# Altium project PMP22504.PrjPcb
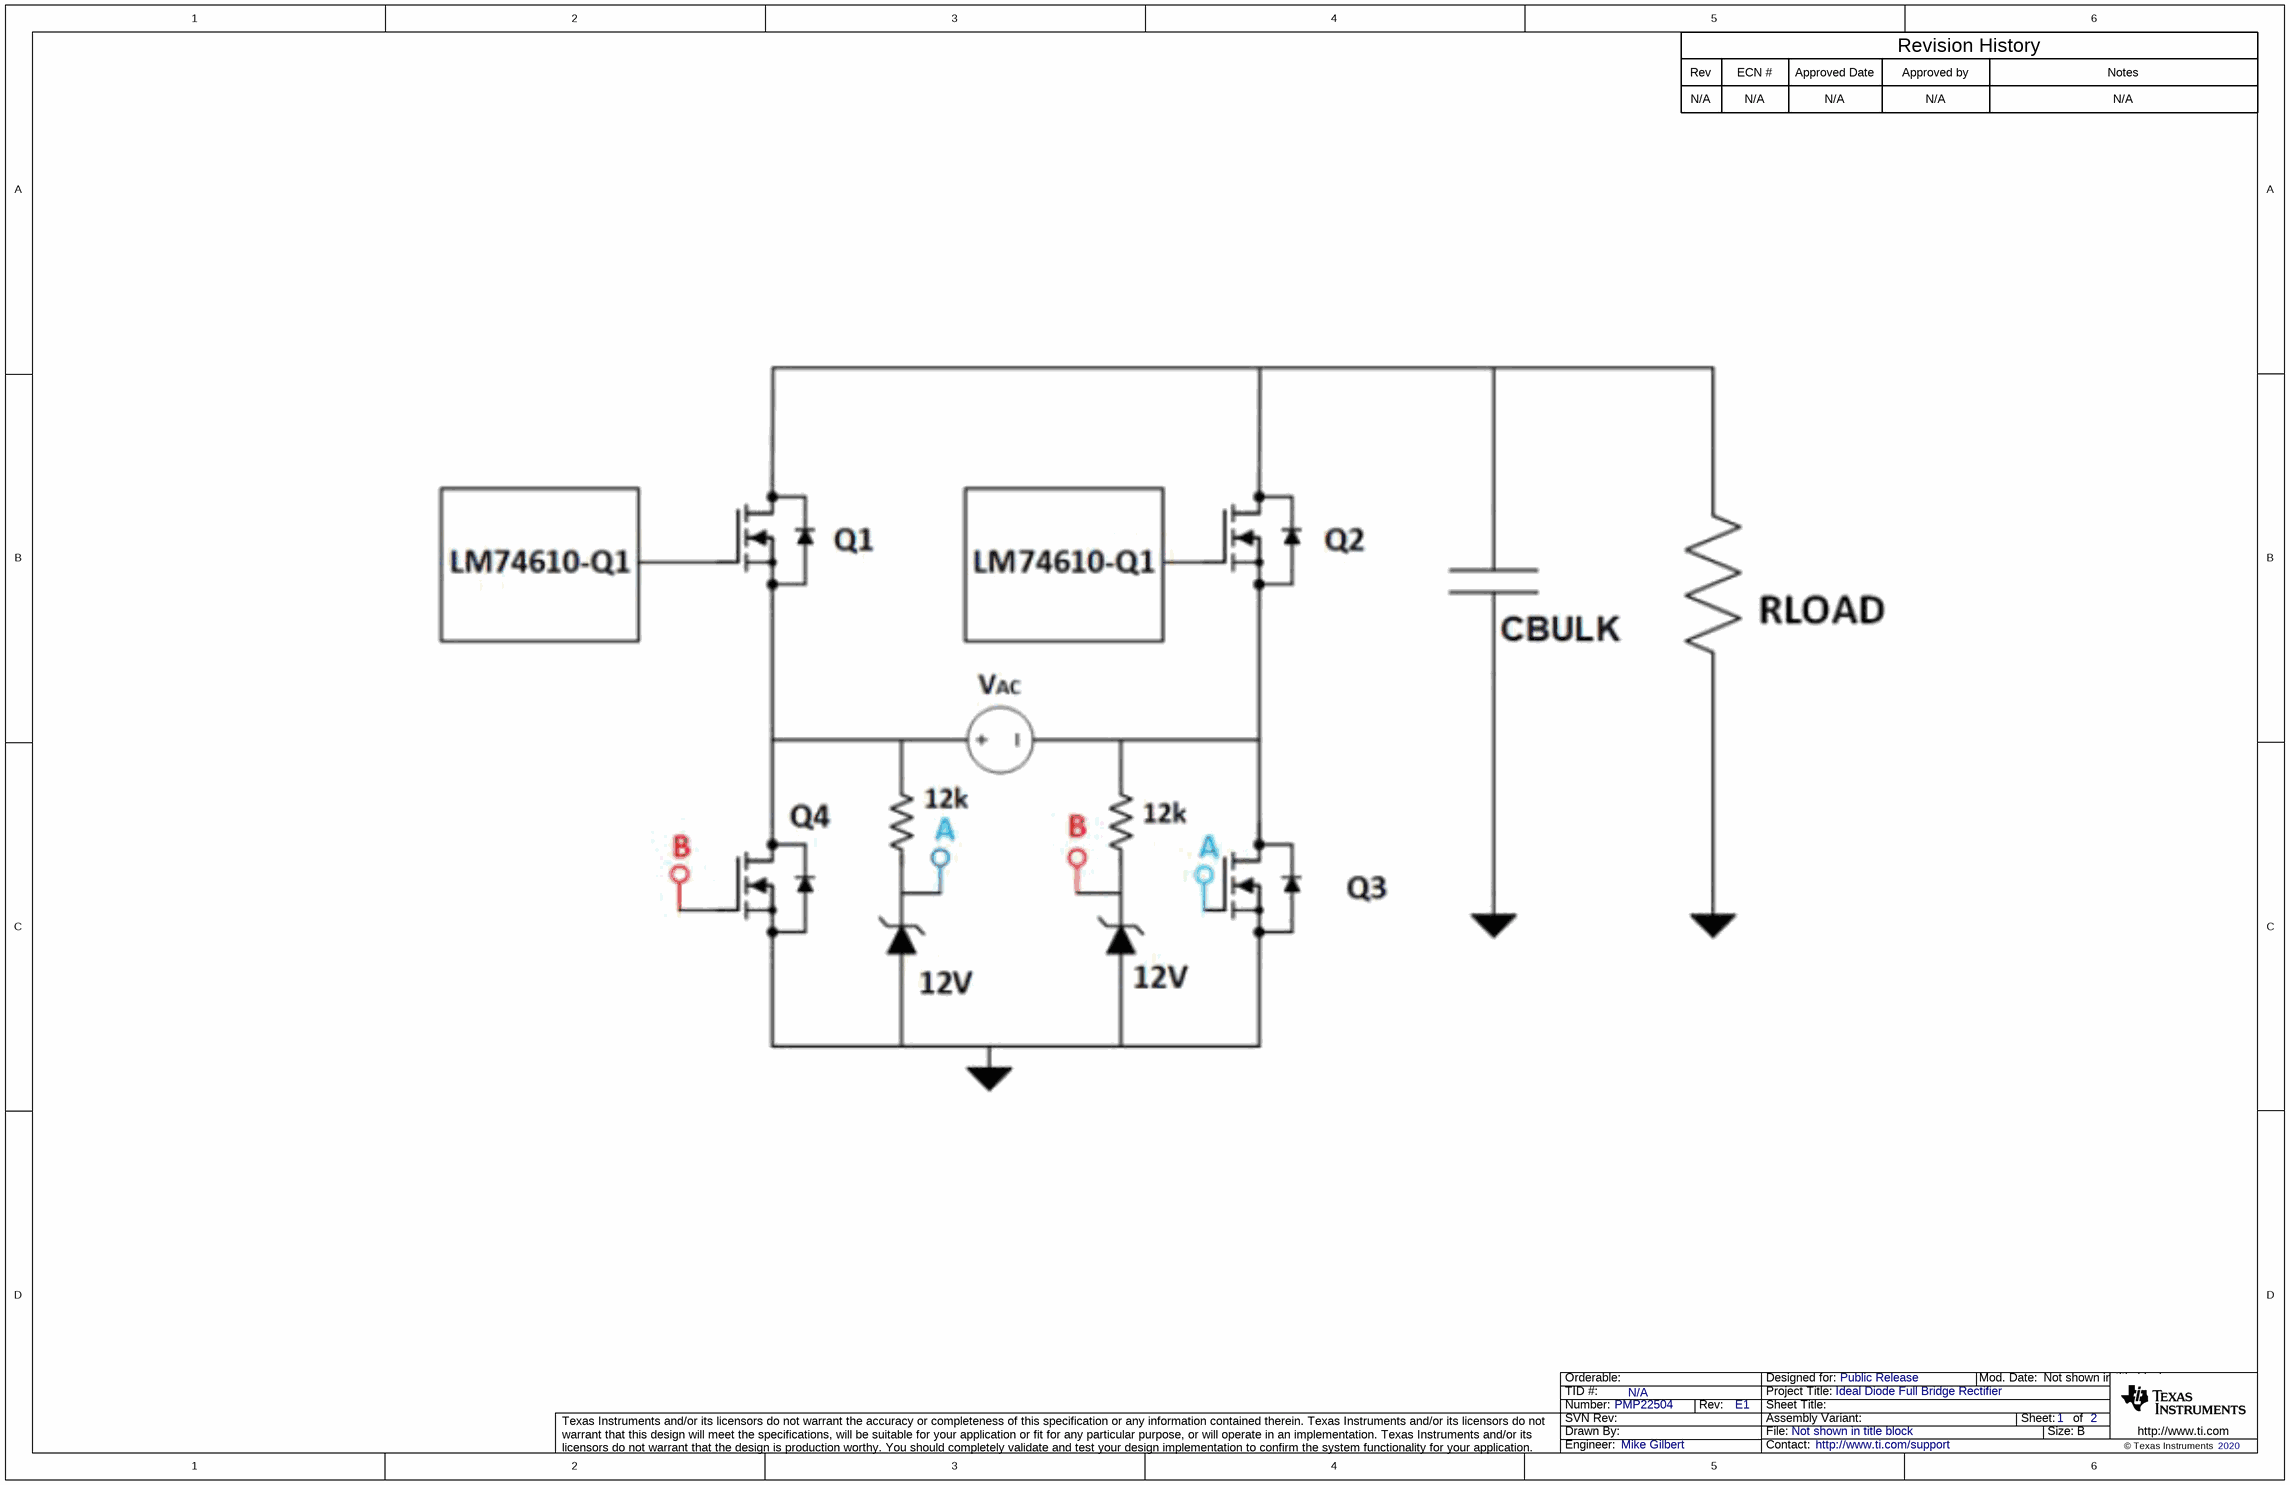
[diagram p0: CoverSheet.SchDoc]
CopyrightYear: 2020; PCB_Layout: Mike Gilbert; PCB_Rev: E1; PRJ_Customer: Public Release; PRJ_Engineer: Mike Gilbert; PRJ_Number: PMP22504; PRJ_Title: Ideal Diode Full Bridge Rectifier; SCH_Rev: E1; TechSupport: http://www.ti.com/support; TID: N/A
2 sheets, 22 parts. Net scope: global (net labels, ports and power ports of the same name join across sheets).
Board file: PMP22504 PCB.PcbDoc
Sheets:
  CoverSheet.SchDoc
  PMP22504.SchDoc

## Sheet CoverSheet.SchDoc
size 431 x 279 mm; Date: Not shown in title block; ApprovedBy: Not shown in title block; CheckedBy: Not shown in title block; Author: Not shown in title block; CompanyName: Not shown in title block; Engineer: Not shown in title block; Organization: Not shown in title block; Address1: Not shown in title block; Address2: Not shown in title block; Address3: Not shown in title block; Address4: Not shown in title block; DocumentNumber: 1; Revision: Use project parameter SCH_Rev; SheetNumber: 1; SheetTotal: 2; PageSetup: Record=PageOptions¦CenterHorizontal=True¦CenterVertical=True¦PrintScale=1.00¦XCorrection=1.00¦YCorrection=1.00¦PrintKind=0¦BorderSize=5000000¦LeftOffset=0¦BottomOffset=0¦Orientation=2¦PaperLength=1000¦PaperWidth=1000¦Scale=100¦PaperSource=15¦PrintQuality=600¦MediaType=1¦DitherType=10¦PaperKind=Letter¦PrintScaleMode=1

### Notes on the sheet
- Rev
- N/A
- ECN #
- Approved Date
- Approved by
- Revision History
- Notes

## Sheet PMP22504.SchDoc
size 431 x 279 mm; Date: Not shown in title block; ApprovedBy: Not shown in title block; CheckedBy: Not shown in title block; Author: Not shown in title block; CompanyName: Not shown in title block; Engineer: Not shown in title block; Organization: Not shown in title block; Address1: Not shown in title block; Address2: Not shown in title block; Address3: Not shown in title block; Address4: Not shown in title block; DocumentNumber: 2; Revision: Use project parameter SCH_Rev; SheetNumber: 2; SheetTotal: 2; PageSetup: Record=PageOptions¦CenterHorizontal=True¦CenterVertical=True¦PrintScale=1.00¦XCorrection=1.00¦YCorrection=1.00¦PrintKind=0¦BorderSize=5000000¦LeftOffset=0¦BottomOffset=0¦Orientation=2¦PaperLength=1000¦PaperWidth=1000¦Scale=100¦PaperSource=15¦PrintQuality=600¦MediaType=1¦DitherType=10¦PaperKind=Letter¦PrintScaleMode=1
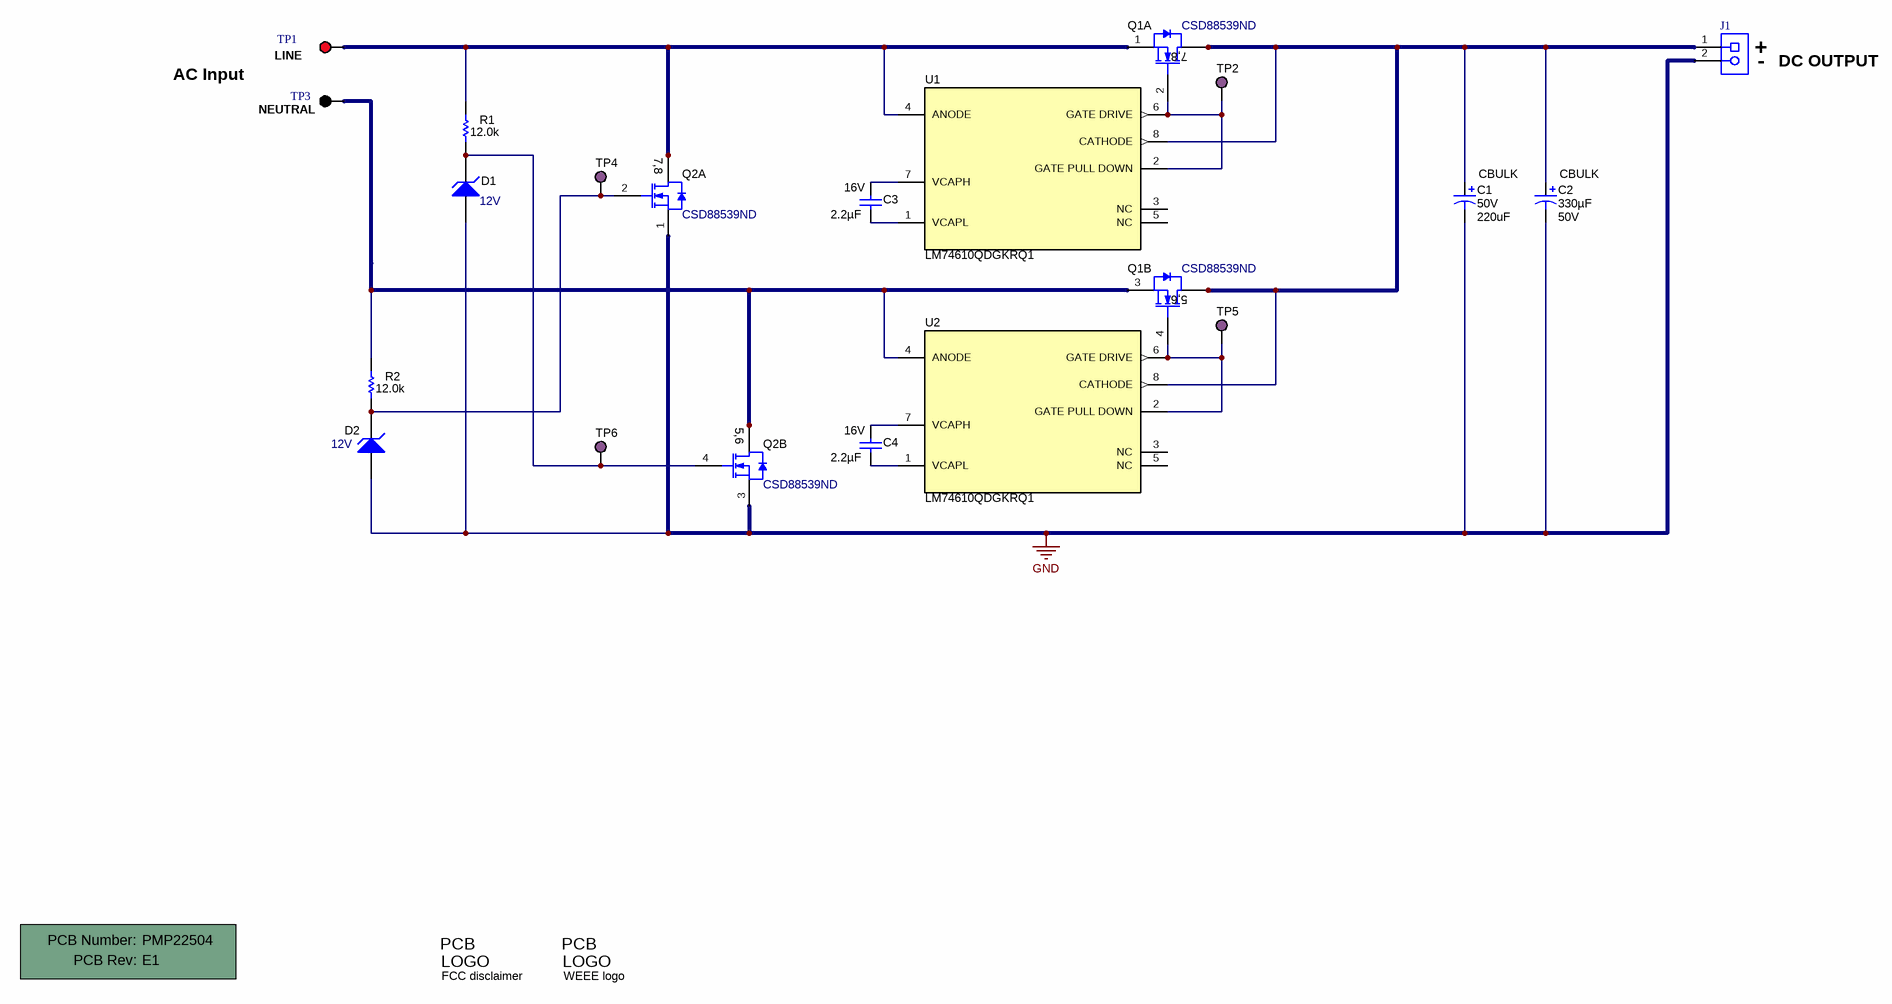
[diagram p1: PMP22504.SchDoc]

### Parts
!PCB1  Printed Circuit Board  (value not drawn)  (mechanical)
C1  CBULK  VDC_V: 50V  ValueDisplayed: 220uF  [SM_RADIAL_G]
C2  CBULK  ValueDisplayed: 330µF  VDC_V: 50V  [SM_RADIAL_G]
C3  VDC_V: 16V  Cap_F: 2.2µF  [0603L]  (hidden comment: GRM188Z71C225KE43)
C4  VDC_V: 16V  Cap_F: 2.2µF  [0603L]  (hidden comment: GRM188Z71C225KE43)
D1  value 12V  [SOD-323]  (hidden comment: MMSZ5242BS-7-F)
D2  value 12V  [SOD-323]  (hidden comment: MMSZ5242BS-7-F)
J1  ED555/2DS  [TERM_BLK_ED555-2DS]  (value not drawn)
Logo2  FCC disclaimer  [FCC_disclaimer]  (no BOM)
Logo3  WEEE logo  [WEEE_Minimum]  (no BOM)
Q1  CSD88539ND  [D0008A_L]  (parts A,B of 2)
Q2  CSD88539ND  [D0008A_L]  (parts A,B of 2)
R1  ValueDisplayed: 12.0k  [0603]  (hidden comment: RC0603FR-0712KL)
R2  ValueDisplayed: 12.0k  [0603]  (hidden comment: RC0603FR-0712KL)
TP1  LINE  [Keystone5010]
TP2  5129  [Keystone5129]  (value not drawn)
TP3  NEUTRAL  [Keystone5011]
TP4  5129  [Keystone5129]  (value not drawn)
TP5  5129  [Keystone5129]  (value not drawn)
TP6  5129  [Keystone5129]  (value not drawn)
U1  LM74610QDGKRQ1  [DGK0008A_N]
U2  LM74610QDGKRQ1  [DGK0008A_N]

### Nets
GND: C1.2(-) C2.2(-) D1.2(A) D2.2(A) J1.2 Q2.1(S) Q2.3(S)
NetC1_1: C1.1(+) C2.1(+) J1.1 Q1.5(D) Q1.6(D) Q1.7(D) Q1.8(D) U1.8(CATHODE) U2.8(CATHODE)
NetC3_1: C3.1 U1.7(VCAPH)
NetC3_2: C3.2 U1.1(VCAPL)
NetC4_1: C4.1 U2.7(VCAPH)
NetC4_2: C4.2 U2.1(VCAPL)
NetD1_1: D1.1(K) Q2.4(G) R1.1 TP6.1
NetD2_1: D2.1(K) Q2.2(G) R2.1 TP4.1
NetQ1_1: Q1.1(S) Q2.7(D) Q2.8(D) R1.2 TP1.1 U1.4(ANODE)
NetQ1_2: Q1.2(G) TP2.1 U1.2(GATE_PULL_DOWN) U1.6(GATE_DRIVE)
NetQ1_3: Q1.3(S) Q2.5(D) Q2.6(D) R2.2 TP3.1 U2.4(ANODE)
NetQ1_4: Q1.4(G) TP5.1 U2.2(GATE_PULL_DOWN) U2.6(GATE_DRIVE)

Not connected (* = marked no-connect by the designer): U1 3(NC) 5(NC); U2 3(NC) 5(NC)

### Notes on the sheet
- AC Input
- (near J1) -
- (near J1) +
- DC OUTPUT

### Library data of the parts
!PCB1 = CMP-0003618-2: Manufacturer: Any; PartNumber: PMP22504
C1 = CMP-0011180-2: CAP, AL, 220 uF, 50 V, +/- 20%, 0.18 ohm, AEC-Q200 Grade 2, SMD; Manufacturer: Panasonic; PartNumber: EEE-FK1H221GP; TaMin_C: -55°C; ESR_ohm: 0.18; Polarized: Y; SizeAreaWB_mm2: 172.2; U/M: EA; Value: 220uF; TaMax_C: 105°C; SizeZ_mm: 10.2; SizeX_mm: 12; SizeY_mm: 10.3; Cap_Case: G; SizeArea_mm2: 123.6; CompType: Capacitor; Cap_F: 220µF; IRMS_A: 670mA; AEC Grade: 2; AEC Category: Q200
C2 = CMP-0860442-1: CAP, AL, 330 µF, 50 V, +/- 20%, 0.12 ohm, AEC-Q200 Grade 2, SMD; PartNumber: EEE-FT1H331AP; Manufacturer: Panasonic; ESR_ohm: 0.12; CompType: Capacitor; U/M: EA; AEC Qualified: Y; TaMax_C: 105°C; Green_Lifecycle: Active; SizeY_mm: 10.3; SizeZ_mm: 10.2; Value: 330uF; AEC Grade: 2; TaMin_C: -55°C; Green_REACh: Passed; SizeArea_mm2: 123.6; AEC Category: Q200; Cap_Case: 10x10.2mm; SizeAreaWB_mm2: 172.2; SizeX_mm: 12
C3 C4 = CMP-0007499-1: CAP, CERM, 2.2 uF, 16 V, +/- 10%, X7R, 0603; Manufacturer: MuRata; TaMin_C: -55°C; Polarized: N; SizeAreaWB_mm2: 4.68; Value1: Unknown; U/M: EA; Value: 2.2uF; TaMax_C: 125°C; SizeZ_mm: 1; SizeX_mm: 1.6; SizeY_mm: 0.8; Cap_Case: 0603; SizeArea_mm2: 1.28; AEC Category: Q200
D1 D2 = CMP-0005831-4: Diode, Zener, 12 V, 200 mW, SOD-323; Manufacturer: Diodes Inc.; Power_W: 200mW; SizeZ_mm: 1; SizeX_mm: 2.7; SizeAreaWB_mm2: 8.695; Value1: 0.2W; RJA_CperW: 350; AEC Category: Q101; SizeArea_mm2: 3.645; SizeY_mm: 1.35
J1 = CMP-0074913-1: Terminal Block, 3.5mm Pitch, 2x1, TH; Manufacturer: On-Shore Technology; Cert_VDE: Y; CNHeader: False; Current_A: 6A; Green_Lifecycle: Active; Shrouded: N; Gender: Female; Green_REACh: Passed; Voltage_V: 150V; Row_Count: 1; Pitch_mm: 3.5; ContactFinish: Brass; CT: True
Logo2 = CMP-0074847-1: FCC_disclaimer; Library Reference: Logo
Logo3 = CMP-0074769-1
Q1 Q2 = CMP-0000829-2: MOSFET, 2-CH, N-CH, 60 V, 6.3 A, D0008A (SOIC-8); Alternate Manufacturer: None; Manufacturer: Texas Instruments; SizeZ_mm: 1.75; ChType: N; Value2: 7.2 nC; VdsMax_V: 60V; SizeX_mm: 4.9; SizeY_mm: 6.2; Vgs_V: 20V; QgTyp_nC: 7.2; Value: 60V; SizeArea_mm2: 30.38; AEC Category: Q101; IdsMax_A: 6.3A; SizeAreaWB_mm2: 56.58; U/M: EA
R1 R2 = CMP-0022779-5: RES, 12.0 k, 1%, 0.1 W, 0603; Manufacturer: Yageo; Power_W: 100mW; TempCo: 100 ppm/C; Value_Code: 12k0; Value: 12.0k; Res_ohm: 12k; SizeX_mm: 1.6; SizeY_mm: 0.8; SizeZ_mm: 1; Value2: 0.1W; SizeArea_mm2: 1.28; AEC Qualified: N; VDC_V: 75V; AEC Category: Q200; SizeAreaWB_mm2: 4.68
TP1 = CMP-0055147-1: Test Point, Multipurpose, Red, TH; Manufacturer: Keystone; CNHeader: FALSE; Green_Lifecycle: Active; Green_REACh: Passed; ContactFinish: Silver; CT: TRUE
TP2 TP4-TP6 = CMP-0055160-1: Test Point, Multipurpose, Purple, TH; Manufacturer: Keystone; CNHeader: FALSE; ContactFinish: Silver; CT: TRUE
TP3 = CMP-0055148-1: Test Point, Multipurpose, Black, TH; Manufacturer: Keystone; CNHeader: FALSE; Green_Lifecycle: Active; Green_REACh: Passed; ContactFinish: Silver; CT: TRUE
U1 U2 = CMP-0076397-2: Zero Iq Reverse Polarity Protection Smart Diode Controller, DGK0008A (VSSOP-8); Manufacturer: Texas Instruments; SizeAreaWB_mm2: 23.6; SizeArea_mm2: 14.7; SizeZ_mm: 1.1; Green_REACh: Passed; SizeY_mm: 3; Green_Lifecycle: Active; CompType: IC; SizeX_mm: 4.9; AEC Category: Q200; AEC Qualified: Y

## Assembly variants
001: not fitted C1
